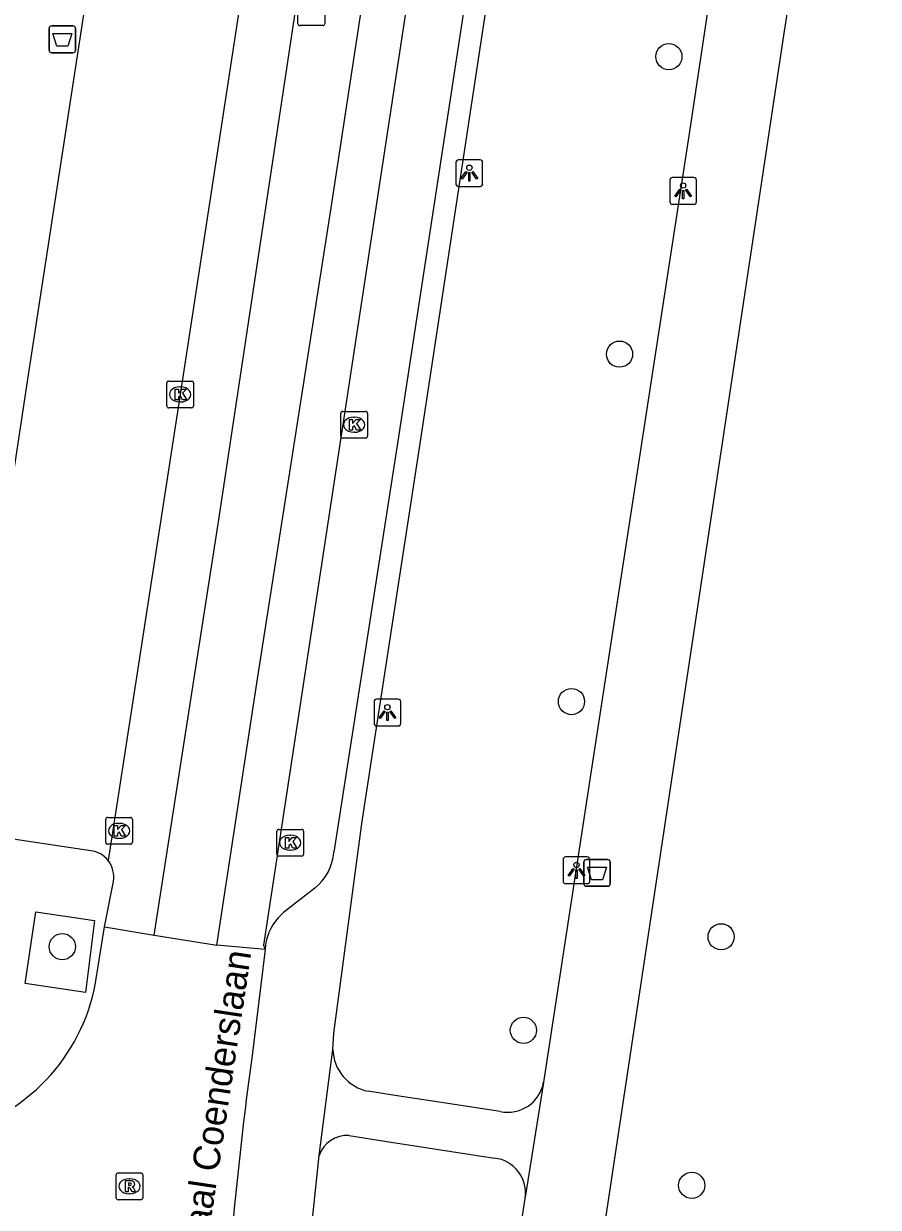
# Model space of a CAD drawing. Extents: x 161084 to 161928, y 385355 to 386522.
# Drawn here: x 161636.96 to 161668.88, y 385456.25 to 385500.45 of the extents above; entities that cross this region are included whole.
import ezdxf

# ---------------------------------------------------------------- set-up
doc = ezdxf.new("R2010")
doc.units = 0
for name, color, linetype in [('IMGEO_Afvalbak', 7, 'Continuous'), ('IMGEO_Boom', 7, 'Continuous'), ('IMGEO_Fietspad_gesloten', 7, 'Continuous'), ('IMGEO_Kolk', 7, 'Continuous'), ('IMGEO_Lichtpunt', 7, 'Continuous'), ('IMGEO_Openbare_ruimte_label', 7, 'Continuous'), ('IMGEO_Rijbaan_lokaal_gesloten', 7, 'Continuous'), ('IMGEO_Rijbaan_lokaal_open', 7, 'Continuous'), ('IMGEO_Rioolput', 7, 'Continuous'), ('IMGEO_Voetpad_open', 7, 'Continuous')]:
    doc.layers.add(name, color=color, linetype=linetype)

msp = doc.modelspace()

# ---------------------------------------------------------------- linework, layer by layer
at = {"layer": 'IMGEO_Afvalbak'}
for p, q in [((161637.908, 385499.461), (161637.908, 385500.261)), ((161637.908, 385500.261), (161637.908, 385499.461)), ((161638.008, 385500.361), (161638.798, 385500.361)), ((161638.798, 385500.361), (161638.008, 385500.361)), ((161638.898, 385500.261), (161638.898, 385499.461)), ((161638.898, 385499.461), (161638.898, 385500.261)), ((161638.798, 385499.361), (161638.008, 385499.361)), ((161638.008, 385499.361), (161638.798, 385499.361)), ((161657.876, 385468.337), (161657.876, 385469.137)), ((161657.876, 385469.137), (161657.876, 385468.337)), ((161657.976, 385469.237), (161658.766, 385469.237)), ((161658.766, 385469.237), (161657.976, 385469.237)), ((161658.866, 385469.137), (161658.866, 385468.337)), ((161658.866, 385468.337), (161658.866, 385469.137)), ((161658.766, 385468.237), (161657.976, 385468.237)), ((161657.976, 385468.237), (161658.766, 385468.237))]:
    msp.add_line(p, q, dxfattribs=at)
for points in [[(161638.051, 385500.075), (161638.755, 385500.075), (161638.606, 385499.605), (161638.2, 385499.605), (161638.051, 385500.075)], [(161658.019, 385468.951), (161658.723, 385468.951), (161658.574, 385468.481), (161658.168, 385468.481), (161658.019, 385468.951)]]:
    msp.add_lwpolyline(points, dxfattribs=at)
for centre, start, end in [((161638.008, 385500.261), 90, 180), ((161638.008, 385500.261), 90, 180), ((161638.798, 385500.261), 0, 90), ((161638.798, 385500.261), 360, 90), ((161638.008, 385499.461), 180, 270), ((161638.008, 385499.461), 180, 270), ((161638.798, 385499.461), 270, 0), ((161638.798, 385499.461), 270, 0), ((161657.976, 385469.137), 90, 180), ((161657.976, 385469.137), 90, 180), ((161658.766, 385469.137), 0, 90), ((161658.766, 385469.137), 360, 90), ((161657.976, 385468.337), 180, 270), ((161657.976, 385468.337), 180, 270), ((161658.766, 385468.337), 270, 0), ((161658.766, 385468.337), 270, 0)]:
    msp.add_arc(centre, 0.1, start, end, dxfattribs=at)
at = {"layer": 'IMGEO_Boom'}
for centre in [(161661.056, 385499.216), (161659.215, 385488.107), (161657.419, 385475.134), (161663.008, 385466.351), (161638.401, 385465.983), (161655.623, 385462.859), (161661.91, 385457.07)]:
    msp.add_circle(centre, 0.489, dxfattribs=at)
at = {"layer": 'IMGEO_Fietspad_gesloten'}
for points in [[(161655.077, 385525.205), (161654.912, 385525.117), (161645.921, 385466.044), (161645.972, 385465.882)], [(161647.816, 385519.194), (161646.455, 385510.418), (161642.802, 385486.602), (161640.112, 385469.197)], [(161639.981, 385466.717), (161640.307, 385468.42)]]:
    msp.add_lwpolyline(points, dxfattribs=at)
msp.add_arc((161639.335, 385468.589), 0.987, 350.1456, 38.031, dxfattribs=at)
at = {"layer": 'IMGEO_Kolk'}
for p, q in [((161642.301, 385486.176), (161642.301, 385487.028)), ((161642.376, 385487.102), (161643.228, 385487.102)), ((161642.789, 385486.882), (161642.814, 385486.882)), ((161643.302, 385487.028), (161643.302, 385486.176)), ((161642.812, 385486.322), (161642.787, 385486.322)), ((161643.228, 385486.102), (161642.376, 385486.102)), ((161648.801, 385485.044), (161648.801, 385485.896)), ((161648.876, 385485.97), (161649.728, 385485.97)), ((161649.802, 385485.896), (161649.802, 385485.044)), ((161649.289, 385485.75), (161649.314, 385485.75)), ((161649.728, 385484.97), (161648.876, 385484.97)), ((161649.312, 385485.19), (161649.287, 385485.19)), ((161640.096, 385470.807), (161640.948, 385470.807)), ((161640.021, 385469.881), (161640.021, 385470.733)), ((161640.509, 385470.587), (161640.534, 385470.587)), ((161641.022, 385470.733), (161641.022, 385469.881)), ((161646.489, 385470.363), (161647.341, 385470.363)), ((161640.532, 385470.027), (161640.507, 385470.027)), ((161646.414, 385469.437), (161646.414, 385470.289)), ((161646.902, 385470.143), (161646.927, 385470.143)), ((161647.415, 385470.289), (161647.415, 385469.437)), ((161640.948, 385469.807), (161640.096, 385469.807)), ((161646.925, 385469.583), (161646.9, 385469.583)), ((161647.341, 385469.363), (161646.489, 385469.363))]:
    msp.add_line(p, q, dxfattribs=at)
for points in [[(161642.301, 385486.176), (161642.301, 385487.028)], [(161642.376, 385487.102), (161643.228, 385487.102)], [(161642.622, 385486.802), (161642.745, 385486.802), (161642.745, 385486.651), (161642.875, 385486.802), (161643.039, 385486.802), (161642.893, 385486.651), (161643.046, 385486.402), (161642.894, 385486.402), (161642.809, 385486.566), (161642.745, 385486.499), (161642.745, 385486.402), (161642.622, 385486.402), (161642.622, 385486.802)], [(161643.302, 385487.028), (161643.302, 385486.176)], [(161643.228, 385486.102), (161642.376, 385486.102)], [(161648.801, 385485.044), (161648.801, 385485.896)], [(161648.876, 385485.97), (161649.728, 385485.97)], [(161649.802, 385485.896), (161649.802, 385485.044)], [(161649.122, 385485.67), (161649.245, 385485.67), (161649.245, 385485.519), (161649.375, 385485.67), (161649.539, 385485.67), (161649.393, 385485.519), (161649.546, 385485.27), (161649.394, 385485.27), (161649.309, 385485.434), (161649.245, 385485.367), (161649.245, 385485.27), (161649.122, 385485.27), (161649.122, 385485.67)], [(161649.728, 385484.97), (161648.876, 385484.97)], [(161640.096, 385470.807), (161640.948, 385470.807)], [(161640.021, 385469.881), (161640.021, 385470.733)], [(161640.342, 385470.507), (161640.465, 385470.507), (161640.465, 385470.356), (161640.595, 385470.507), (161640.759, 385470.507), (161640.613, 385470.356), (161640.766, 385470.107), (161640.614, 385470.107), (161640.529, 385470.271), (161640.465, 385470.204), (161640.465, 385470.107), (161640.342, 385470.107), (161640.342, 385470.507)], [(161641.022, 385470.733), (161641.022, 385469.881)], [(161646.489, 385470.363), (161647.341, 385470.363)], [(161646.414, 385469.437), (161646.414, 385470.289)], [(161646.735, 385470.063), (161646.858, 385470.063), (161646.858, 385469.912), (161646.988, 385470.063), (161647.152, 385470.063), (161647.006, 385469.912), (161647.159, 385469.663), (161647.007, 385469.663), (161646.922, 385469.827), (161646.858, 385469.76), (161646.858, 385469.663), (161646.735, 385469.663), (161646.735, 385470.063)], [(161647.415, 385470.289), (161647.415, 385469.437)], [(161640.948, 385469.807), (161640.096, 385469.807)], [(161647.341, 385469.363), (161646.489, 385469.363)]]:
    msp.add_lwpolyline(points, dxfattribs=at)
for centre, start, end in [((161642.378, 385487.026), 91.552, 178.448), ((161642.378, 385487.026), 91.552, 178.448), ((161643.226, 385487.026), 1.552, 88.448), ((161643.226, 385487.026), 1.552, 88.448), ((161642.378, 385486.178), 181.552, 268.448), ((161642.378, 385486.178), 181.552, 268.448), ((161643.226, 385486.178), 271.552, 358.448), ((161643.226, 385486.178), 271.552, 358.448), ((161648.878, 385485.894), 91.552, 178.448), ((161648.878, 385485.894), 91.552, 178.448), ((161649.726, 385485.894), 1.552, 88.448), ((161649.726, 385485.894), 1.552, 88.448), ((161648.878, 385485.046), 181.552, 268.448), ((161648.878, 385485.046), 181.552, 268.448), ((161649.726, 385485.046), 271.552, 358.448), ((161649.726, 385485.046), 271.552, 358.448), ((161640.098, 385470.731), 91.552, 178.448), ((161640.098, 385470.731), 91.552, 178.448), ((161640.946, 385470.731), 1.552, 88.448), ((161640.946, 385470.731), 1.552, 88.448), ((161646.491, 385470.287), 91.552, 178.448), ((161646.491, 385470.287), 91.552, 178.448), ((161647.339, 385470.287), 1.552, 88.448), ((161647.339, 385470.287), 1.552, 88.448), ((161640.098, 385469.883), 181.552, 268.448), ((161640.098, 385469.883), 181.552, 268.448), ((161640.946, 385469.883), 271.552, 358.448), ((161640.946, 385469.883), 271.552, 358.448), ((161646.491, 385469.439), 181.552, 268.448), ((161646.491, 385469.439), 181.552, 268.448), ((161647.339, 385469.439), 271.552, 358.448), ((161647.339, 385469.439), 271.552, 358.448)]:
    msp.add_arc(centre, 0.0765, start, end, dxfattribs=at)
for centre, major_axis, ratio, start_param, end_param in [((161642.788, 385486.602), (-0.387, 0.002), 0.722429, 4.712389, 7.853982), ((161642.813, 385486.602), (-0.39, 0.002), 0.717154, 1.570796, 4.712389), ((161649.288, 385485.47), (-0.387, 0.002), 0.722429, 4.712389, 7.853982), ((161649.313, 385485.47), (-0.39, 0.002), 0.717154, 1.570796, 4.712389), ((161640.508, 385470.307), (-0.387, 0.002), 0.722429, 4.712389, 7.853982), ((161640.533, 385470.307), (-0.39, 0.002), 0.717154, 1.570796, 4.712389), ((161646.901, 385469.863), (-0.387, 0.002), 0.722429, 4.712389, 7.853982), ((161646.926, 385469.863), (-0.39, 0.002), 0.717154, 1.570796, 4.712389)]:
    msp.add_ellipse(centre, major_axis=major_axis, ratio=ratio, start_param=start_param, end_param=end_param, dxfattribs=at)
at = {"layer": 'IMGEO_Lichtpunt'}
for p, q in [((161653.105, 385495.269), (161653.105, 385494.462)), ((161653.105, 385495.269), (161653.105, 385494.462)), ((161654.007, 385495.364), (161653.199, 385495.364)), ((161654.007, 385495.364), (161653.199, 385495.364)), ((161654.101, 385494.462), (161654.101, 385495.269)), ((161654.101, 385494.462), (161654.101, 385495.269)), ((161661.994, 385494.702), (161661.186, 385494.702)), ((161661.994, 385494.702), (161661.186, 385494.702)), ((161653.199, 385494.368), (161654.007, 385494.368)), ((161653.199, 385494.368), (161654.007, 385494.368)), ((161661.092, 385494.607), (161661.092, 385493.8)), ((161661.092, 385494.607), (161661.092, 385493.8)), ((161662.088, 385493.8), (161662.088, 385494.607)), ((161662.088, 385493.8), (161662.088, 385494.607)), ((161661.186, 385493.706), (161661.994, 385493.706)), ((161661.186, 385493.706), (161661.994, 385493.706)), ((161650.947, 385475.223), (161650.139, 385475.223)), ((161650.947, 385475.223), (161650.139, 385475.223)), ((161650.045, 385475.128), (161650.045, 385474.321)), ((161650.045, 385475.128), (161650.045, 385474.321)), ((161651.041, 385474.321), (161651.041, 385475.128)), ((161651.041, 385474.321), (161651.041, 385475.128)), ((161650.139, 385474.227), (161650.947, 385474.227)), ((161650.139, 385474.227), (161650.947, 385474.227)), ((161657.106, 385469.237), (161657.106, 385468.43)), ((161657.106, 385469.237), (161657.106, 385468.43)), ((161658.008, 385469.332), (161657.2, 385469.332)), ((161658.008, 385469.332), (161657.2, 385469.332)), ((161658.102, 385468.43), (161658.102, 385469.237)), ((161658.102, 385468.43), (161658.102, 385469.237)), ((161657.2, 385468.336), (161658.008, 385468.336)), ((161657.2, 385468.336), (161658.008, 385468.336))]:
    msp.add_line(p, q, dxfattribs=at)
for points in [[(161653.479, 385494.933), (161653.518, 385494.905), (161653.33, 385494.643), (161653.292, 385494.67), (161653.479, 385494.933)], [(161653.581, 385494.885), (161653.628, 385494.885), (161653.628, 385494.563), (161653.581, 385494.563), (161653.581, 385494.885)], [(161653.691, 385494.905), (161653.729, 385494.932), (161653.916, 385494.67), (161653.877, 385494.642), (161653.691, 385494.905)], [(161661.466, 385494.271), (161661.505, 385494.243), (161661.317, 385493.981), (161661.279, 385494.008), (161661.466, 385494.271)], [(161661.568, 385494.223), (161661.615, 385494.223), (161661.615, 385493.901), (161661.568, 385493.901), (161661.568, 385494.223)], [(161661.678, 385494.243), (161661.716, 385494.27), (161661.903, 385494.008), (161661.864, 385493.98), (161661.678, 385494.243)], [(161650.419, 385474.792), (161650.458, 385474.764), (161650.27, 385474.502), (161650.232, 385474.529), (161650.419, 385474.792)], [(161650.521, 385474.744), (161650.568, 385474.744), (161650.568, 385474.422), (161650.521, 385474.422), (161650.521, 385474.744)], [(161650.631, 385474.764), (161650.669, 385474.791), (161650.856, 385474.529), (161650.817, 385474.501), (161650.631, 385474.764)], [(161657.48, 385468.901), (161657.519, 385468.873), (161657.331, 385468.611), (161657.293, 385468.638), (161657.48, 385468.901)], [(161657.582, 385468.853), (161657.629, 385468.853), (161657.629, 385468.531), (161657.582, 385468.531), (161657.582, 385468.853)], [(161657.692, 385468.873), (161657.73, 385468.9), (161657.917, 385468.638), (161657.878, 385468.61), (161657.692, 385468.873)]]:
    msp.add_lwpolyline(points, dxfattribs=at)
for centre in [(161653.604, 385495.067), (161661.591, 385494.405), (161650.544, 385474.926), (161657.605, 385469.035)]:
    msp.add_circle(centre, 0.0994, dxfattribs=at)
for centre, start, end in [((161653.199, 385495.269), 90, 180), ((161653.199, 385495.269), 90, 180), ((161654.007, 385495.269), 0, 90), ((161654.007, 385495.269), 0, 90), ((161661.186, 385494.607), 90, 180), ((161661.186, 385494.607), 90, 180), ((161661.994, 385494.607), 0, 90), ((161661.994, 385494.607), 0, 90), ((161653.199, 385494.462), 180, 270), ((161653.199, 385494.462), 180, 270), ((161654.007, 385494.462), 270, 0), ((161654.007, 385494.462), 270, 360), ((161661.186, 385493.8), 180, 270), ((161661.186, 385493.8), 180, 270), ((161661.994, 385493.8), 270, 0), ((161661.994, 385493.8), 270, 360), ((161650.139, 385475.128), 90, 180), ((161650.139, 385475.128), 90, 180), ((161650.947, 385475.128), 0, 90), ((161650.947, 385475.128), 0, 90), ((161650.139, 385474.321), 180, 270), ((161650.139, 385474.321), 180, 270), ((161650.947, 385474.321), 270, 0), ((161650.947, 385474.321), 270, 360), ((161657.2, 385469.237), 90, 180), ((161657.2, 385469.237), 90, 180), ((161658.008, 385469.237), 0, 90), ((161658.008, 385469.237), 0, 90), ((161657.2, 385468.43), 180, 270), ((161657.2, 385468.43), 180, 270), ((161658.008, 385468.43), 270, 0), ((161658.008, 385468.43), 270, 360)]:
    msp.add_arc(centre, 0.0946, start, end, dxfattribs=at)
at = {"layer": 'IMGEO_Rijbaan_lokaal_gesloten'}
for points in [[(161644.173, 385466.039), (161645.687, 385475.984), (161648.418, 385493.406), (161650.81, 385509.078), (161653.229, 385525.292), (161656.101, 385544.122), (161657.035, 385551.607), (161657.676, 385557.376)], [(161641.834, 385466.406), (161644.23, 385481.84), (161647.175, 385501.347), (161649.95, 385519.187), (161652.131, 385533.824), (161654.621, 385550.774)], [(161641.834, 385466.406), (161644.173, 385466.039)]]:
    msp.add_lwpolyline(points, dxfattribs=at)
at = {"layer": 'IMGEO_Rijbaan_lokaal_open'}
for points in [[(161639.642, 385464.626), (161639.981, 385466.717)], [(161639.981, 385466.717), (161641.834, 385466.406)], [(161645.972, 385465.882), (161644.173, 385466.039)], [(161645.972, 385465.882), (161645.495, 385461.921), (161645.284, 385460.364)]]:
    msp.add_lwpolyline(points, dxfattribs=at)
for centre, radius, start, end in [((161632.635, 385465.918), 7.125, 283.2484, 349.549), ((161833.966, 385437.297), 190.087, 173.02986, 177.50061)]:
    msp.add_arc(centre, radius, start, end, dxfattribs=at)
at = {"layer": 'IMGEO_Rioolput'}
for p, q in [((161647.202, 385500.447), (161647.202, 385501.299)), ((161648.203, 385501.299), (161648.203, 385500.447)), ((161648.129, 385500.373), (161647.277, 385500.373)), ((161640.484, 385457.535), (161641.336, 385457.535)), ((161640.409, 385456.609), (161640.409, 385457.461)), ((161640.897, 385457.315), (161640.922, 385457.315)), ((161641.41, 385457.461), (161641.41, 385456.609)), ((161640.92, 385456.755), (161640.895, 385456.755)), ((161641.336, 385456.535), (161640.484, 385456.535))]:
    msp.add_line(p, q, dxfattribs=at)
for points in [[(161647.202, 385500.447), (161647.202, 385501.299)], [(161648.203, 385501.299), (161648.203, 385500.447)], [(161648.129, 385500.373), (161647.277, 385500.373)], [(161640.484, 385457.535), (161641.336, 385457.535)], [(161640.409, 385456.609), (161640.409, 385457.461)], [(161640.998, 385457.233), (161640.746, 385457.235), (161640.746, 385456.835)], [(161640.924, 385457.154), (161640.87, 385457.154), (161640.87, 385457.073)], [(161640.87, 385457.073), (161640.922, 385457.073)], [(161641.41, 385457.461), (161641.41, 385456.609)], [(161640.746, 385456.835), (161640.87, 385456.835), (161640.87, 385456.997), (161640.881, 385456.997)], [(161640.928, 385456.968), (161640.999, 385456.835), (161641.139, 385456.835), (161641.074, 385456.961)], [(161641.336, 385456.535), (161640.484, 385456.535)]]:
    msp.add_lwpolyline(points, dxfattribs=at)
for centre, radius, start, end in [((161647.279, 385500.449), 0.0765, 181.552, 268.448), ((161647.279, 385500.449), 0.0765, 181.552, 268.448), ((161648.127, 385500.449), 0.0765, 271.552, 358.448), ((161648.127, 385500.449), 0.0765, 271.552, 358.448), ((161640.486, 385457.459), 0.0765, 91.552, 178.448), ((161640.486, 385457.459), 0.0765, 91.552, 178.448), ((161641.334, 385457.459), 0.0765, 1.552, 88.448), ((161641.334, 385457.459), 0.0765, 1.552, 88.448), ((161640.906, 385457.262), 0.19, 274.7715, 282.9687), ((161640.93, 385457.058), 0.0964, 77.0061, 93.1865), ((161640.944, 385457.115), 0.0378, 276.6634, 79.6772), ((161640.997, 385457.123), 0.109, 350.3612, 89.416), ((161640.995, 385457.123), 0.112, 277.5842, 350.9817), ((161640.88, 385456.944), 0.0533, 26.0293, 88.6989), ((161640.979, 385456.908), 0.108, 29.5134, 73.7905), ((161640.486, 385456.611), 0.0765, 181.552, 268.448), ((161640.486, 385456.611), 0.0765, 181.552, 268.448), ((161641.334, 385456.611), 0.0765, 271.552, 358.448), ((161641.334, 385456.611), 0.0765, 271.552, 358.448)]:
    msp.add_arc(centre, radius, start, end, dxfattribs=at)
for centre, major_axis, ratio, start_param, end_param in [((161640.896, 385457.035), (-0.387, 0.002), 0.722429, 4.712389, 7.853982), ((161640.921, 385457.035), (-0.39, 0.002), 0.717154, 1.570796, 4.712389)]:
    msp.add_ellipse(centre, major_axis=major_axis, ratio=ratio, start_param=start_param, end_param=end_param, dxfattribs=at)
at = {"layer": 'IMGEO_Voetpad_open'}
for points in [[(161656.38, 385460.922), (161658.19, 385472.711), (161661.817, 385496.26), (161663.625, 385508.283), (161667.803, 385536.052), (161668.116, 385538.133), (161668.239, 385538.924)], [(161648.507, 385462.144), (161648.548, 385462.752), (161649.596, 385470.673), (161651.761, 385484.769), (161655.178, 385507.25), (161657.879, 385524.571), (161659.14, 385524.383), (161661.208, 385537.956)], [(161656.719, 385442.697), (161665.355, 385500), (161668.88, 385522.726)], [(161656.511, 385521.404), (161654.564, 385508.627), (161650.93, 385484.859), (161648.543, 385469.513)], [(161639.461, 385469.565), (161634.565, 385470.3), (161635.266, 385475.049), (161637.136, 385487.334), (161640.593, 385509.875), (161642.132, 385519.767)], [(161647.832, 385468.172), (161646.666, 385467.256), (161646.466, 385467.062)], [(161639.601, 385466.954), (161639.269, 385464.266), (161637.008, 385464.609), (161637.407, 385467.281), (161639.601, 385466.954)], [(161647.993, 385458.185), (161648.507, 385462.144)], [(161655.683, 385456.575), (161655.699, 385456.628), (161656.38, 385460.904), (161656.38, 385460.922)], [(161654.755, 385459.827), (161653.046, 385460.089), (161650.74, 385460.441), (161649.829, 385460.581)], [(161649.115, 385458.928), (161650.52, 385458.711), (161652.934, 385458.337), (161654.544, 385458.088)], [(161646.866, 385440.852), (161647.015, 385446.776), (161647.198, 385449.946), (161647.537, 385453.796), (161647.993, 385458.185)], [(161653.085, 385439.584), (161655.028, 385452.288), (161655.683, 385456.575)]]:
    msp.add_lwpolyline(points, dxfattribs=at)
for centre, radius, start, end in [((161639.338, 385468.587), 0.986, 38.2272, 82.8152), ((161646.658, 385469.653), 1.89, 308.3894, 355.7454), ((161647.93, 385465.756), 1.962, 138.2595, 176.3078), ((161650.153, 385462.196), 1.647, 181.7969, 258.6528), ((161655.037, 385461.162), 1.364, 258.0731, 349.8747), ((161649.033, 385457.833), 1.098, 85.7166, 161.3093), ((161654.388, 385456.785), 1.312, 350.7925, 83.1531)]:
    msp.add_arc(centre, radius, start, end, dxfattribs=at)

# ---------------------------------------------------------------- texts
at = {"layer": 'IMGEO_Openbare_ruimte_label'}
msp.add_text('Generaal Coenderslaan', height=1, rotation=81.4324, dxfattribs=at).set_placement((161643.347, 385451.73))

doc.saveas('drawing.dxf')
